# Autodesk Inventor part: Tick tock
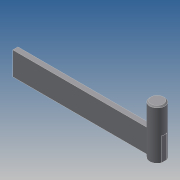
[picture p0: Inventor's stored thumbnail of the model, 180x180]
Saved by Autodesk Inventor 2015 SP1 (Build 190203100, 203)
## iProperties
Created: 2015-01
Part Number: Tick tock
Material: Generic
Document SubType Name: Modeling
Designer: Steve Brooks
Density: 1 g/cm^3
Appearance: Default
Author: Steve Brooks
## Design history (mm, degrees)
sketch "Sketch1"
  geometry: C1 r 5.75 at (0, 0); 1 further point
  constraints: 1 centre point, 1 coincident
  dimensions: "d0" = 11.5 diameter of C1
extrude "Extrusion1" new body sketch "Sketch1" distance "d1" = 38; taper "d2" = 0 deg
sketch "Sketch2"
  geometry: L1 (9, -2)-(-9, -2); L2 (-9, -2)-(-9, 2); L3 (-9, 2)-(9, 2); L4 (9, 2)-(9, -2); L5 (9, -2)-(-9, 2); L6 (-9, -2)-(9, 2); C1 r 5.75 at (0, 0) reference
  constraints: 12 end point, 2 midpoint, 2 parallel, 1 horizontal, 1 perpendicular
extrude "Extrusion2" cut sketch "Sketch2" distance "d3" = 18; taper "d4" = 0 deg
sketch "Sketch3"
  geometry: L1 (-5.391, 2)-(109.609, 2); L2 (109.609, 2)-(109.609, -2); L3 (109.609, -2)-(-5.391, -2); L4 (-5.391, -2)-(-5.391, 2)
  constraints: 8 end point, 2 parallel, 1 horizontal, 1 perpendicular
  dimensions: "d5" = 115 distance of L2.end L3.end; "d6" = 4 distance of L1.end L2.end
extrude "Extrusion3" new body sketch "Sketch3" distance "d7" = 18; taper "d8" = 0 deg
chamfer "Chamfer1" distance "d9" = 1; stored, may be unused: second distance "d10" = 2, angle "d11" = 45 deg
body "Solid1"
body "Solid2"
